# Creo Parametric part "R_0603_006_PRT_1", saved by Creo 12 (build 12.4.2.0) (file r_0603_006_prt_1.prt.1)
Units: Custom; MM, KILOGRAM, SECS

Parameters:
  PTC_WM_ITERATION = "0"
  PTC_WM_VERSION = "-.0"
  PTC_WM_LIFECYCLE_STATE = "In Work"
  PTC_WM_LIFECYCLE = "MO_CADDocument"
  PTC_WM_CREATED_BY = "Maximilian Roepper (Z0017RMS: MO)"
  PTC_WM_CREATED_ON = "18-Sep-26 11:36:42 AM"
  PTC_WM_MODIFIED_BY = "Maximilian Roepper (Z0017RMS: MO)"
  PTC_WM_MODIFIED_ON = "18-Sep-26 11:36:46 AM"
  PDMLINKNUMBER = "PDM000071454879"
  PTC_WM_NAME = "r_0603_006_prt_1.prt"
  PTC_WM_NUMBER = "PDM000071454879"

Other parameters: WEIGHT, WEIGHT_FACTOR, WEIGHT_ADD, _MASS_TEMP, _DIFF_TEMP, MC_ERRORS, SUPPLIER

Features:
  1. coordinate system
  2. datum plane "PRT_YZ"
  3. datum plane "PRT_XY"
  4. datum plane "PRT_XZ"
  5. coordinate system
  6. datum axis
  7. datum axis
  8. datum axis
  9. coordinate system
  10. imported feature
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
Other named items: PRT, SIEMENS_MO, DRW_VIEW_ORG, PRT_X, PRT_Y, PRT_Z, CS0, ROUGH_GROB

Layers: 00_STD_CSYS-KSYS, 01_STD_PLANES-EBENEN, 02_STD_AXES-ACHSEN, 03_STD_CSYS-KSYS, 24_IMPORT_FEAT-IMPORT_KE

Surfaces: 18 plane, 8 cylinder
